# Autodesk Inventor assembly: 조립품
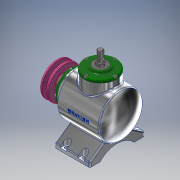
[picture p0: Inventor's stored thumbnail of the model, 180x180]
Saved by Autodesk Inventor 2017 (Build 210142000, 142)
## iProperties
Part Number: 조립품
Material: 일반
Document SubType Name: Assembly
Designer: MRC
Author: MRC
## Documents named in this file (17)
- C:\Users\MRC\Desktop\730108V1006\조립품.iam
- C:\Users\MRC\Desktop\730108V1006\V-벨트풀리.ipt
- C:\Users\MRC\Desktop\730108V1006\메인 베벨기어.ipt
- C:\Users\MRC\Desktop\730108V1006\메인 축.ipt
- 메인 축.ipt
- C:\Users\MRC\Desktop\730108V1006\베어링 6203.ipt
- C:\Users\MRC\Desktop\730108V1006\본체.ipt
- C:\Users\MRC\Desktop\730108V1006\볼트 M4 x 10.ipt
- C:\Users\MRC\Desktop\730108V1006\서브 베벨기어.ipt
- C:\Users\MRC\Desktop\730108V1006\서브 축.ipt
- 서브 축.ipt
- C:\Users\MRC\Desktop\730108V1006\오일실 17 x 32 x 8.ipt
- C:\Users\MRC\Desktop\730108V1006\와셔 4 x 16.ipt
- C:\Users\MRC\Desktop\730108V1006\육각볼트 M4 x 8.ipt
- C:\Users\MRC\Desktop\730108V1006\커버.ipt
- C:\Users\MRC\Desktop\730108V1006\키 4 x 4 x 14.ipt
- C:\Users\MRC\Desktop\730108V1006\키 5 x 5 x 14.ipt
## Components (1 placed, 1 different names)
1. V-벨트풀리:1
